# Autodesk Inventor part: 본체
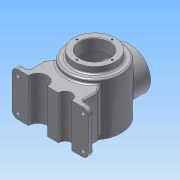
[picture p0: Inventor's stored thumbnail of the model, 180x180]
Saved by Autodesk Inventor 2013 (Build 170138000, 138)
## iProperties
Created: 2018-08
Part Number: 본체
Material: 알루미늄 6061
Document SubType Name: Modeling
Designer: Administrator
Density: 2.71 g/cm^3
Mass: 1885.19 g
Surface Area: 1089.38 cm^2
Volume: 695.643 cm^3
Author: Administrator
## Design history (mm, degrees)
sketch "스케치1"
  geometry: C1 r 50 at (0, 0); 1 further point
  constraints: 1 centre point, 1 coincident
  dimensions: "d0" = 100 diameter of C1
extrude "돌출1" new body sketch "스케치1" stored distance "d1" = 108; taper "d2" = 0 deg
sketch "스케치2"
  geometry: L1 (-50, -54)-(50, -54) reference; L2 (116, 62)-(-116, 62); L3 (50, 54)-(-50, 54) reference; A1 r 116 centre (0, 62) between (-116, 62) and (116, 62); 1 further point
  constraints: 2 end point, 2 point on circle, 1 centre point, 1 parallel, 1 tangent, 1 vertical alignment
  dimensions: "d4" = 232 diameter of A1; "d129" = 108 distance between parallel lines of L1 L3 (derived)
revolve "회전1" sketch "스케치2" stored, may be unused: angle "d5" = 90 deg
node "작업 평면1"
sketch "스케치3"
  geometry: L1 (-70, -82)-(70, -82); L2 (70, -82)-(70, -72); L3 (70, -72)-(-70, -72); L4 (-70, -72)-(-70, -82); 2 further points
  constraints: 8 end point, 2 parallel, 1 horizontal, 1 midpoint, 1 perpendicular, 1 vertical alignment
  dimensions: "d26" = 140 distance of L3.end L2.end; "d27" = 10 distance of L2.end L1.end; "d28" = 82 distance from line of L1 point (0, 0)
extrude "돌출2" join sketch "스케치3" distance "d29" = 80; taper "d30" = 0 deg
sketch "스케치4"
  geometry: L1 (70, -72)-(-70, -72) reference; L2 (-56.207, -85.689)-(32.46, -85.689); L3 (-50, -43.437)-(-29.918, -14.758); L4 (-50, -72)-(-50, -43.437); L5 (50, -43.437)-(29.918, -14.758); L6 (70, -72)-(139.88, -72); L7 (50, -72)-(50, -43.437); L8 (29.918, -14.758)-(-29.918, -14.758); L9 (-50, -72)-(50, -72); 1 further point
  constraints: 16 end point, 3 perpendicular, 2 horizontal, 2 point on line, 1 collinear
  dimensions: "d34" = 20 distance from line of L4 L1.end; "d35" = 125 deg angle of L6 L5; "d36" = 20 distance from line of L1.start L7; "d37" = 28.67954 vertical distance of L5.start L5.end; "d38" = 28.67954 vertical distance of L3.start L3.end; "d39" = 59.83674 distance of L5.end L3.end; "d40" = 28.56296 distance from line of L1 L3.start
extrude "돌출3" join sketch "스케치4" distance "d41" = 80; taper "d42" = 0 deg
sketch "스케치5"
  geometry: C1 r 50 at (0, 0) reference; C2 r 38 at (0, 0)
  constraints: 1 centre point, 1 coincident
  dimensions: "d43" = 76 diameter of C2
extrude "돌출4" join sketch "스케치5" distance "d44" = 12; taper "d45" = 0 deg
sketch "스케치6"
  geometry: C1 r 38 at (0, 0) reference; C2 r 27 at (0, 0)
  constraints: 1 centre point, 1 coincident
  dimensions: "d46" = 54 diameter of C2
extrude "돌출5" cut sketch "스케치6" distance "d47" = 22; taper "d48" = 0 deg
sketch "스케치7"
  geometry: L1 (0, 44)-(0, -59.052); L2 (-27, 44)-(27, 44) reference; L3 (0, 44)-(40, 44); L4 (40, 44)-(40, -36.163); A1 r 116 centre (0, 62) between (-50, -42.671) and (50, -42.671) reference; A2 r 106 centre (0, 62) between (0, -44) and (40, -36.163); 1 further point
  constraints: 6 end point, 2 point on circle, 2 point on line, 1 centre point, 1 midpoint, 1 perpendicular, 1 vertical
  dimensions: "d49" = 10 radial gap between concentric circles of A1 A2; "d51" = 80 diameter of L4 L1
revolve "회전2" sketch "스케치7" stored, may be unused: angle "d52" = 90 deg
node "작업 평면2"
sketch "스케치8"
  geometry: L1 (120, 8)-(20, 8) reference; L2 (0, 0)-(0, -80) reference; C1 r 38 at (70, -42); 1 further point
  constraints: 1 centre point
  dimensions: "d54" = 76 diameter of C1; "d55" = 50 distance from line of L1 C1.centre; "d56" = 70 distance from line of L2 C1.centre
extrude "돌출6" join sketch "스케치8" stored distance "d57" = 70 (= d56); taper "d58" = 0 deg
sketch "스케치9"
  geometry: C1 r 38 at (0, 0) reference; C2 r 27 at (0, 0); 1 further point
  constraints: 1 centre point, 1 coincident
  dimensions: "d59" = 54 diameter of C2
extrude "돌출7" cut sketch "스케치9" stored distance "d60" = 70 (= d56); taper "d61" = 0 deg
sketch "스케치10"
  geometry: L1 (-70, -82)-(70, -82) reference; C1 r 17.5 at (-22.5, -82); C2 r 12.5 at (27.5, -82); A1 r 50 centre (0, 0) between (-40.304, -29.59) and (40.304, -29.59) reference
  constraints: 2 centre point, 2 point on line
  dimensions: "d62" = 35 diameter of C1; "d63" = 25 diameter of C2; "d64" = 22.5 horizontal distance of A1.centre C1.centre; "d65" = 27.5 horizontal distance of C2.centre A1.centre
extrude "돌출8" cut sketch "스케치10" stored distance "d66" = 70 (= d56); taper "d67" = 0 deg
fillet "모깎기1" dims "d68" = 10
hole "구멍1" diameter "d71" = 8; stored, may be unused: countersink angle "d75" = 90 deg, drill point angle "d77" = 0 deg; dims "d69" = 10, "d70" = 10, "d72" = 6, "d73" = 4, "d74" = 2, "d76" = 8
hole "구멍2" diameter "d80" = 8; stored, may be unused: countersink angle "d84" = 90 deg, drill point angle "d86" = 0 deg; dims "d78" = 10, "d79" = 10, "d81" = 6, "d82" = 4, "d83" = 2, "d85" = 8
hole "구멍3" diameter "d89" = 8; stored, may be unused: countersink angle "d93" = 90 deg, drill point angle "d95" = 0 deg; dims "d87" = 10, "d88" = 10, "d90" = 6, "d91" = 4, "d92" = 2, "d94" = 8
hole "구멍4" diameter "d98" = 8; stored, may be unused: countersink angle "d102" = 90 deg, drill point angle "d104" = 0 deg; dims "d96" = 10, "d97" = 10, "d99" = 6, "d100" = 4, "d101" = 2, "d103" = 8
sketch "스케치11"
  geometry: C1 r 27 at (0, 0) reference; C2 r 38 at (0, 0) reference; A1 r 32.5 centre (0, 0) between (0, 32.5) and (0, -32.5); 3 further points
  constraints: 4 point on circle, 2 horizontal alignment, 2 vertical alignment, 1 centre point, 1 coincident
  dimensions: "d105" = 65 diameter of A1
hole "구멍5" sketch "스케치11" at (0, 32.5), (32.5, 0), (0, -32.5), (-32.5, 0) diameter "d106" = 3.242; stored, may be unused: countersink angle "d110" = 90 deg, drill point angle "d112" = 118 deg; dims "d107" = 8, "d108" = 4, "d109" = 2, "d111" = 10
sketch "스케치12"
  geometry: C1 r 27 at (0, 0) reference; C2 r 38 at (0, 0) reference; A1 r 32.5 centre (0, 0) between (0, 32.5) and (0, -32.5); 2 further points
  constraints: 4 point on circle, 2 horizontal alignment, 2 vertical alignment, 1 centre point, 1 coincident
  dimensions: "d113" = 65 diameter of A1
hole "구멍6" sketch "스케치12" at (0, 32.5), (0, -32.5), (32.5, 0), (-32.5, 0) diameter "d114" = 3.242; stored, may be unused: countersink angle "d118" = 90 deg, drill point angle "d120" = 118 deg; dims "d115" = 8, "d116" = 4, "d117" = 2, "d119" = 10
node "작업 평면3"
sketch "스케치13"
  geometry: C1 r 32.5 at (0, 0); 1 further point
  constraints: 1 centre point, 1 coincident, 1 other
  dimensions: "d122" = 65 diameter of C1
feature "엠보싱1" sketch "스케치13" dims "d123" = 0.5, "d124" = 0
fillet "모깎기2" dims "d125" = 3
chamfer "모따기1" distance "d126" = 1; stored, may be unused: second distance "d127" = 2, angle "d128" = 45 deg
node "솔리드1"
other parameters: "d6" = -8, "d32" = 55 deg, "d53" = -147, "d121" = -108
